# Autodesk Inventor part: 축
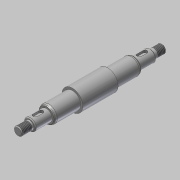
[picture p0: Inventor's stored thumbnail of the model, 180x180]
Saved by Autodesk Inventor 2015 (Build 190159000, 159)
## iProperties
Created: 2020-05
Part Number: 축
Material: 강철, 연강
Document SubType Name: Modeling
Designer: mduedu
Density: 1 g/cm^3
Appearance: 강철
Author: mduedu
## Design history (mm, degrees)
sketch "스케치1"
  geometry: L1 (0, 0)-(21, 0); L2 (21, 0)-(21, 12.5); L3 (21, 12.5)-(0, 12.5); L4 (0, 12.5)-(0, 0); L5 (21, 0)-(52, 0); L6 (52, 0)-(52, 10); L7 (52, 10)-(21, 10); L8 (21, 10)-(21, 0); L9 (52, 0)-(72, 0); L10 (72, 0)-(72, 7); L11 (72, 7)-(52, 7); L12 (52, 7)-(52, 0); L13 (72, 0)-(86, 0); L14 (86, 0)-(86, 5); L15 (86, 5)-(72, 5); L16 (72, 5)-(72, 0); L17 (0, 0)-(-21, 0); L18 (-21, 0)-(-21, 12.5); L19 (-21, 12.5)-(0, 12.5); L20 (-21, 0)-(-52, 0); L21 (-52, 0)-(-52, 10); L22 (-52, 10)-(-21, 10); L23 (-21, 10)-(-21, 0); L24 (-52, 0)-(-72, 0); L25 (-72, 0)-(-72, 7); L26 (-72, 7)-(-52, 7); L27 (-52, 7)-(-52, 0); L28 (-72, 0)-(-86, 0); L29 (-86, 0)-(-86, 5); L30 (-86, 5)-(-72, 5); L31 (-72, 5)-(-72, 0)
  constraints: 62 end point, 11 symmetric about line, 8 parallel, 4 horizontal, 4 perpendicular
  dimensions: "d0" = 172 distance between parallel lines of L14 L29; "d2" = 25 diameter of L3 L1; "d3" = 20 diameter of L7 L5; "d4" = 14 diameter of L11 L9; "d5" = 10 diameter of L15 L13; "d6" = 42 distance of L2.end L18.end; "d7" = 31 distance of L6.end L7.end; "d8" = 20 distance of L10.end L11.end; "d9" = 14 distance of L14.end L15.end (derived)
revolve "회전1" sketch "스케치1" stored, may be unused: angle "d10" = 90 deg
sketch "스케치2"
  geometry: L1 (72, -5)-(72, -7) reference; L2 (72, -7)-(52, -7) reference; L3 (52, -7)-(52, -10) reference; L4 (52, -10)-(21, -10) reference; L5 (21, -10)-(21, -12.5) reference; L6 (21, -12.5)-(-21, -12.5) reference; L7 (-21, -12.5)-(-21, -10) reference; L8 (-21, -10)-(-52, -10) reference; L9 (-52, -10)-(-52, -7) reference; L10 (-52, -7)-(-72, -7) reference; L11 (-72, -7)-(-72, -5) reference; L12 (-72, -5)-(-86, -5) reference; L13 (-86, -5)-(-86, 5) reference; L14 (-86, 5)-(-72, 5) reference; L15 (-72, 5)-(-72, 7) reference; L16 (-72, 7)-(-52, 7) reference; L17 (-52, 7)-(-52, 10) reference; L18 (-52, 10)-(-21, 10) reference; L19 (-21, 10)-(-21, 12.5) reference; L20 (-21, 12.5)-(21, 12.5) reference; L21 (21, 12.5)-(21, 10) reference; L22 (21, 10)-(52, 10) reference; L23 (52, 10)-(52, 7) reference; L24 (52, 7)-(72, 7) reference; L25 (72, 7)-(72, 5) reference; L26 (72, 5)-(86, 5) reference; L27 (86, 5)-(86, -5) reference; L28 (86, -5)-(72, -5) reference; L29 (-86, 0)-(86, 0); L30 (0, -12.5)-(0, 12.5); L31 (-52, 8.85)-(-50.008, 10); L32 (-50.008, 10)-(-52, 10); L33 (-52, 10)-(-52, 8.85); 1 further point
  constraints: 10 end point, 4 midpoint, 2 collinear, 2 point on line
  dimensions: "d11" = 17.7 diameter of L31.start L29; "d12" = 30 deg angle of L31 L32
revolve "회전2" sketch "스케치2" stored, may be unused: angle "d13" = 90 deg
fillet "모깎기1" dims "d14" = 4, "d15" = 0.5
node "작업 평면1"
sketch "스케치3"
  geometry: L1 (-6, 2.5)-(6, 2.5); L2 (6, 2.5)-(6, -2.5); L3 (6, -2.5)-(-6, -2.5); L4 (-6, -2.5)-(-6, 2.5); L5 (-10, 8.561)-(-10, -8.561) reference; 2 further points
  constraints: 8 end point, 2 parallel, 1 horizontal, 1 horizontal alignment, 1 midpoint, 1 perpendicular
  dimensions: "d16" = 5 distance of L1.end L2.end; "d18" = 4 distance between parallel lines of L4 L5; "d19" = 12 distance of L1.start L1.end
extrude "돌출1" cut sketch "스케치3" distance "d20" = 3; taper "d21" = 0 deg
fillet "모깎기2" dims "d22" = 2.5
fillet "모깎기3" dims "d23" = 2.5
feature "스레드1" dims "d24" = 12, "d25" = 0
feature "스레드2" dims "d26" = 10, "d27" = 0
chamfer "모따기1" distance "d28" = 1; stored, may be unused: second distance "d29" = 2, angle "d30" = 45 deg
chamfer "모따기2" distance "d31" = 1; stored, may be unused: second distance "d32" = 2, angle "d33" = 45 deg
node "솔리드1"
mirror "대칭1"
mirror "대칭2"
node "절단 모서리 투영1"
